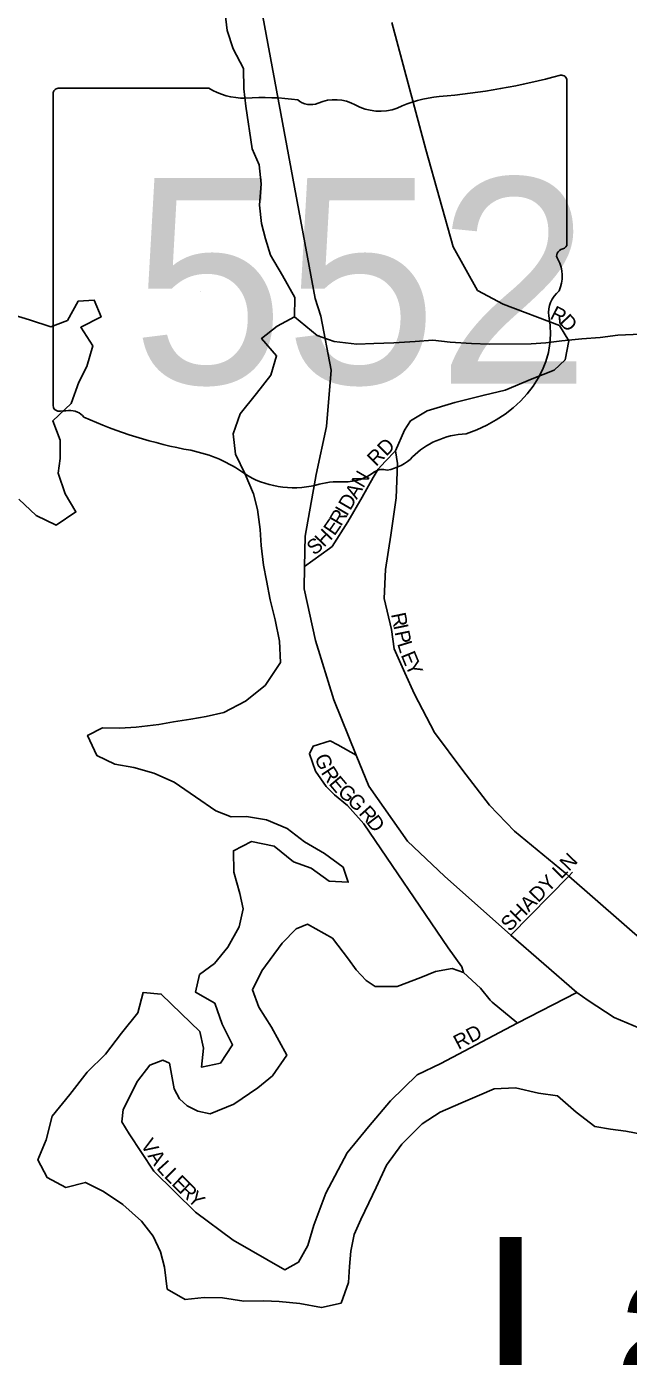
# Model space of a CAD drawing. Extents: x 1578669 to 1989827, y 208020 to 553079.
# Drawn here: x 1819126 to 1821165, y 402632 to 407134 of the extents above; entities that cross this region are included whole.
import ezdxf

# ---------------------------------------------------------------- set-up
doc = ezdxf.new("R2010")
doc.units = 0
for name, color, linetype in [('GM_X_County_Subdivision', 7, 'Continuous'), ('GM_X_County_Subdivision_Text', 7, 'Continuous'), ('GM_X_Major_Lake', 7, 'Continuous'), ('GM_X_Major_Lake_Text', 7, 'Continuous'), ('GM_X_Minor_River', 7, 'Continuous'), ('GM_X_State_Location', 7, 'Continuous'), ('GM_X_State_Route', 7, 'Continuous'), ('GM_X_State_Shield', 7, 'Continuous'), ('GM_X_Township_Subdivision', 7, 'Continuous'), ('GM_X_Township_Subdivision_Text', 7, 'Continuous')]:
    doc.layers.add(name, color=color, linetype=linetype)

msp = doc.modelspace()

# ---------------------------------------------------------------- linework, layer by layer
at = {"layer": 'GM_X_County_Subdivision'}
for points in [[(1820067.4, 405305.9), (1820152, 405367.7), (1820160.9, 405374.2), (1820214.3, 405457.7), (1820262.5, 405540.9), (1820300.5, 405607.2), (1820317.2, 405636.2), (1820341.2, 405661.5), (1820376.3, 405697.8)], [(1820243.1, 404668), (1820180.9, 404702.1), (1820154.8, 404716.2), (1820096.5, 404698.2), (1820084.5, 404672.1), (1820104.5, 404613.9), (1820140.6, 404561.7), (1820168.7, 404533.5), (1820212.9, 404497.4), (1820269.1, 404435.1), (1820554, 404015.1), (1820600.2, 403950.9), (1820606.9, 403931.7)], [(1820767, 404058.2), (1820962.8, 404258.2), (1820976, 404271.8)], [(1820990.1, 403864.5), (1820788.6, 403760.1), (1820529.7, 403623.7), (1820449.3, 403585.6), (1820358.9, 403497.3), (1820284.5, 403409), (1820212.1, 403320.8), (1820139.7, 403184.3), (1820099.5, 403075.9), (1820079.4, 403007.7), (1820047.2, 402951.5), (1820001, 402925.4), (1819826.3, 403026), (1819697.8, 403120.5), (1819557.3, 403259.1), (1819473, 403385.7), (1819448.9, 403425.9), (1819453, 403468.1), (1819501.2, 403564.4), (1819543.4, 403618.5), (1819587.7, 403634.6), (1819609.7, 403624.5), (1819625.8, 403538.2), (1819643.8, 403504), (1819669.9, 403479.9), (1819706, 403461.8), (1819748.2, 403453.7), (1819828.6, 403485.8), (1819909, 403541.9), (1819959.2, 403582), (1820007.4, 403652.2), (1819955.3, 403746.7), (1819913.2, 403815), (1819891.1, 403873.2), (1819923.3, 403937.4), (1819991.6, 404031.7), (1820039.9, 404079.9), (1820078.1, 404095.9), (1820162.4, 404047.6), (1820216.6, 403977.3), (1820242.7, 403941.2), (1820276.8, 403905), (1820306.9, 403884.9), (1820381.2, 403884.8), (1820461.6, 403914.8), (1820511.8, 403934.9), (1820568, 403944.9), (1820606.9, 403931.7), (1820664.4, 403878.5), (1820696.5, 403838.3), (1820703.2, 403831.5), (1820786.6, 403762.1)]]:
    msp.add_lwpolyline(points, dxfattribs=at)
at = {"layer": 'GM_X_Major_Lake'}
for points in [[(1819649.4, 403793.4), (1819712.5, 403732.2), (1819725.6, 403675.9), (1819718.5, 403611.8), (1819782.8, 403624.9), (1819823.9, 403686.4), (1819789, 403757.1), (1819764.2, 403827.7), (1819698.7, 403864.8), (1819711.7, 403924.7), (1819762.4, 403962), (1819807.4, 404017.5), (1819846.6, 404087), (1819859.6, 404146.9), (1819848.5, 404199.2), (1819827.7, 404271.8), (1819826.9, 404343.9), (1819887.5, 404375.1), (1819965.3, 404359.8), (1820030.5, 404306.6), (1820090.3, 404285.6), (1820151.6, 404240.6), (1820215.6, 404237.5), (1820198.4, 404287.9), (1820135.1, 404335), (1820067.7, 404374.2), (1820008.4, 404419.3), (1819938.8, 404448.4), (1819870.9, 404459.5), (1819818.8, 404458.4), (1819767, 404479.2), (1819697.7, 404526.4), (1819626.4, 404575.7), (1819556.9, 404606.9), (1819489.1, 404626), (1819425.2, 404637), (1819363.6, 404666.1), (1819332.7, 404734.7), (1819383.2, 404760), (1819441.3, 404759.1), (1819497.4, 404762.2), (1819573.6, 404771), (1819623.9, 404780.2), (1819682.1, 404789.3), (1819734.3, 404798.5), (1819794.6, 404811.6), (1819867.4, 404850.6), (1819934.3, 404903.6), (1819985.7, 404981), (1819982.9, 405053.2), (1819968.1, 405125.6), (1819951.2, 405194.1), (1819938.3, 405258.5), (1819929.1, 405310.7), (1819920.2, 405377), (1819917.1, 405431.2), (1819908.2, 405499.5), (1819895.1, 405551.9), (1819866.2, 405618.5), (1819833.3, 405687.2), (1819826.4, 405755.5), (1819849.6, 405823.3), (1819904.8, 405892.5), (1819953.9, 405953.9), (1819973, 406019.8), (1819921.9, 406078.7), (1819974.7, 406120), (1820033.3, 406151.2), (1820034.4, 406217.3), (1819993.6, 406292.1), (1819952.6, 406361), (1819935.5, 406415.4), (1819922.4, 406467.7), (1819915.4, 406530), (1819920.6, 406602), (1819913.7, 406666.3), (1819890.6, 406720.8), (1819868.9, 406865.5), (1819861.9, 406923.8), (1819861, 406992), (1819826.1, 407058.7), (1819805.1, 407121.2), (1819798.2, 407187.5)], [(1819072.1, 406160.4), (1819135.9, 406141.3), (1819207.6, 406118.1), (1819264, 406139.3), (1819301.2, 406204.9), (1819355.3, 406208), (1819378.4, 406151.5), (1819309.7, 406116.5), (1819350.7, 406053.7), (1819329.5, 405983.9), (1819302.6, 405930.2), (1819277.4, 405858.4), (1819214.3, 405799.2), (1819239.2, 405734.7), (1819240.2, 405672.5), (1819233.4, 405622.5), (1819256.2, 405552), (1819293.3, 405491.2), (1819226.4, 405446.2), (1819158.9, 405479.3), (1819099.7, 405534.4)], [(1821214.8, 403383.6), (1821156.9, 403394.6), (1821104.9, 403401.4), (1821051, 403410.3), (1820987.7, 403459.4), (1820924.5, 403514.5), (1820860.6, 403523.6), (1820782.8, 403540.8), (1820710.6, 403538), (1820660.2, 403516.7), (1820597.7, 403489.6), (1820527.1, 403458.7), (1820466.3, 403419.5), (1820397.1, 403350.5), (1820345.8, 403279.1), (1820310.5, 403203.5), (1820285.6, 403151.7), (1820258.7, 403096), (1820235.8, 403044.3), (1820224.8, 402988.3), (1820219.9, 402936.2), (1820217, 402882.2), (1820191.8, 402812.4), (1820125.5, 402797.4), (1820051.6, 402810.6), (1819981.6, 402817.7), (1819929.6, 402820.5), (1819861.5, 402819.6), (1819789.6, 402830.8), (1819727.5, 402831.8), (1819663.3, 402824.8), (1819601.8, 402859.8), (1819593, 402934.1), (1819579.9, 402986.5), (1819554.7, 403039), (1819515.5, 403089.8), (1819452.4, 403146.9), (1819387, 403190), (1819325.5, 403221.1), (1819259.1, 403204.1), (1819195.6, 403237.2), (1819164.5, 403297.8), (1819191.7, 403365.6), (1819213, 403445.4), (1819272.3, 403518.7), (1819331.7, 403593.9), (1819392.8, 403655.1), (1819448, 403726.4), (1819503.3, 403795.7), (1819520.4, 403863.6), (1819582.4, 403858.6), (1819649.4, 403793.4)]]:
    msp.add_lwpolyline(points, dxfattribs=at)
at = {"layer": 'GM_X_Minor_River'}
msp.add_lwpolyline([(1820033.3, 406151.2), (1820110.1, 406088.3), (1820168.3, 406068.5), (1820244.5, 406058.9), (1820302.5, 406061.2), (1820370.6, 406063.5), (1820442.7, 406067.9), (1820502.8, 406072.2), (1820560.9, 406066.5), (1820633, 406060.9), (1820693.1, 406059.2), (1820835.3, 406059.9), (1820885.3, 406064.2), (1820939.4, 406070.5), (1821007.4, 406076.8), (1821069.5, 406081.2), (1821129.5, 406089.5), (1821181.6, 406091.8), (1821233.6, 406096.1), (1821305.7, 406106.5), (1821367.7, 406120.8), (1821441.7, 406139.2), (1821493.7, 406161.5), (1821571.7, 406192)], dxfattribs=at)
at = {"layer": 'GM_X_State_Route'}
msp.add_lwpolyline([(1819916.8, 407217.3), (1820103.7, 406214.2), (1820123.3, 406153.8), (1820158, 405970.9), (1820142.5, 405780.3), (1820107.1, 405617.9), (1820069.4, 405409.4), (1820067.4, 405305.9), (1820065.9, 405230.8), (1820104.8, 405055.8), (1820167.4, 404854.6), (1820243.1, 404668), (1820285.6, 404562.6), (1820416.6, 404377), (1820542.2, 404257.6), (1820767, 404058.2), (1820990.1, 403864.5), (1821028.7, 403836.5), (1821116.5, 403779.7), (1821202.6, 403742.9)], dxfattribs=at)
at = {"layer": 'GM_X_State_Shield'}
for p, q in [((1819743, 406925.8), (1819233.3, 406925.8)), ((1820956.4, 406399.3), (1820956.4, 406952)), ((1819216.2, 406907.7), (1819216.2, 405851)), ((1820956.2, 406399.4), (1820956.4, 406399.3))]:
    msp.add_line(p, q, dxfattribs=at)
for centre, major_axis, start_param, end_param in [((1820336.5, 408366.4), (1845.5, 0), 4.814394, 5.042369), ((1820937.1, 406954.3), (19.4, 0), 6.141152, 7.989035), ((1819236.1, 406909.9), (20.2, 0), 1.712693, 3.28349), ((1819864.3, 407048.5), (195.5, 0), 4.042523, 4.731795), ((1819929.2, 406332.6), (702, 0), 1.404758, 1.657858), ((1820088.5, 406915.4), (56.4, 0), 3.836095, 5.185415), ((1820171.3, 406793.3), (117.3, 0), 0.950623, 2.079405), ((1820571.9, 406603.1), (371.3, 0), 1.699011, 2.107814), ((1820322.7, 406960.8), (141.1, 0), 4.081561, 5.145723), ((1820935.7, 406397.1), (20.7, 0), 5.05454, 6.418171), ((1820951.9, 406358.7), (30, 0), 1.883978, 3.671073), ((1820761.2, 406288.8), (180, 0), 5.934695, 6.695948), ((1821025.8, 406168), (130.9, 0), 2.387724, 3.262537), ((1820439.9, 406097.6), (461.6, 0), 5.101752, 6.440018), ((1819236.3, 405848.7), (20.3, 0), 3.00124, 4.508301), ((1819239.4, 405956.8), (155.2, 0), 4.665946, 4.897461), ((1819271.2, 405790.1), (56, 0), 0.519207, 1.627899), ((1819977.8, 406739.4), (1332.7, 0), 4.195997, 4.488961), ((1820634.5, 405554.4), (252.8, 0), 1.647645, 2.488434), ((1819580.4, 405376.3), (417, 0), 0.823519, 1.323587), ((1820314.2, 405748.6), (149.1, 0), 4.937069, 5.64225), ((1820031.4, 405784.8), (264.6, 0), 4.026481, 4.996735), ((1820203.6, 405705.7), (141, 0), 4.691044, 5.507374), ((1820331.1, 405603.4), (39.7, 0), 1.147584, 2.315152), ((1820184.3, 405419.5), (217.4, 0), 1.495662, 1.94098)]:
    msp.add_ellipse(centre, major_axis=major_axis, ratio=0.8, start_param=start_param, end_param=end_param, dxfattribs=at)
at = {"layer": 'GM_X_Township_Subdivision'}
for points in [[(1820376.3, 405697.8), (1820406.9, 405767.6), (1820427.1, 405799.3), (1820483.7, 405833.1), (1820577, 405861.5), (1820676.1, 405886.6), (1820747.9, 405903.1), (1820839.1, 405941.8), (1820913.9, 405971.7), (1820951, 406006.5), (1820963.5, 406071), (1820931.1, 406122.1), (1820741.3, 406194.1), (1820653.8, 406241.1), (1820571.5, 406388.3), (1820479.1, 406718.3), (1820363.3, 407148.1)], [(1821230.9, 404024.6), (1820962.8, 404258.2), (1820951.9, 404267.8), (1820779.2, 404410.5), (1820694.9, 404498.9), (1820604.6, 404615.4), (1820508.3, 404744), (1820440.1, 404874.6), (1820408, 404946.9), (1820371.9, 405027.2), (1820361.9, 405093.5), (1820337.9, 405197.9), (1820341.9, 405296.3), (1820360.1, 405412.7), (1820378.2, 405539.2), (1820382.4, 405655.7), (1820376.3, 405697.8)]]:
    msp.add_lwpolyline(points, dxfattribs=at)

# ---------------------------------------------------------------- texts
at = {"layer": 'GM_X_County_Subdivision_Text'}
for s, rotation, p in [('RD', 45, (1820309.9, 405643.1)), ('N', 59.6736, (1820266.8, 405569.4)), ('A', 59.6736, (1820244.6, 405531.4)), ('D', 59.6736, (1820222.4, 405493.4)), ('R', 59.6736, (1820191.3, 405440.3)), ('I', 59.6736, (1820211.3, 405474.4)), ('E', 55.3441, (1820169, 405407.8)), ('S', 38.0263, (1820099.8, 405342.2)), ('H', 46.6852, (1820133.7, 405369.4)), ('G', 289.7347, (1820101.4, 404661.7)), ('R', 303.2422, (1820121.9, 404608.8)), ('E', 310.1945, (1820147.6, 404570.4)), ('G', 319.6616, (1820176.7, 404537.1)), ('G', 315.2937, (1820209.5, 404509.3)), ('R', 311.684, (1820249.2, 404469.3)), ('D', 307.3114, (1820274.9, 404440.5)), ('SHADY LN', 45.5801, (1820763, 404067.8)), ('RD', 27.8967, (1820589.3, 403669.2)), ('V', 302.4896, (1819510.5, 403349)), ('A', 303.4555, (1819534.7, 403311.1)), ('L', 312.0021, (1819563.9, 403268)), ('L', 315.189, (1819589.5, 403239.6)), ('E', 315.3669, (1819614.6, 403214.7)), ('R', 315.3745, (1819639.7, 403190)), ('Y', 315.3658, (1819667.9, 403162.2))]:
    msp.add_text(s, height=50, rotation=rotation, dxfattribs=at).set_placement(p)
at = {"layer": 'GM_X_Major_Lake_Text'}
msp.add_text('Lake', height=599.99, rotation=359.9989, dxfattribs=at).set_placement((1820662.6, 402436.5))
at = {"layer": 'GM_X_State_Location'}
for s in ['s', 'r']:
    msp.add_text(s, height=1, dxfattribs=at).set_placement((1820066.7, 406309.1))
msp.add_text('552', height=1, rotation=0, dxfattribs=at).set_placement((1819713.7, 406236.3))
at = {"layer": 'GM_X_State_Shield'}
msp.add_text('552', height=696.1, dxfattribs=at).set_placement((1819481.9, 405925.5))
at = {"layer": 'GM_X_Township_Subdivision_Text'}
for s, rotation, p in [('R', 333.0331, (1820896.1, 406146.9)), ('D', 313.547, (1820927.8, 406131.6)), ('R', 281.6385, (1820360.4, 405145.1)), ('I', 281.6624, (1820368.4, 405106.3)), ('P', 281.6636, (1820372.8, 405084.7)), ('L', 287.074, (1820381.2, 405045.4)), ('E', 292.2292, (1820393.1, 405007.2)), ('Y', 294.4771, (1820407.3, 404972.6))]:
    msp.add_text(s, height=50, rotation=rotation, dxfattribs=at).set_placement(p)

doc.saveas('drawing.dxf')
